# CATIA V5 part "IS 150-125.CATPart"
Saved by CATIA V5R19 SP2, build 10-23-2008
Part number: IS 150-125
Bounding box of the stored display mesh (mm): x -15.868 to 15.868, y -15.868 to 15.868, z 0 to 300
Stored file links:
  C:\Users\Bora\Desktop\3D Katı model\IS serisi\IS 150\IS 150-125.CATPart
  C:\Program Files\Dassault Systemes\B19\intel_a\reffiles\standard\MetricThickPitch.txt
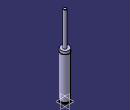
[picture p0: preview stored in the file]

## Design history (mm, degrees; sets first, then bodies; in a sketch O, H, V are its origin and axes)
Body1 (main body)
  Sketch1 on yz-plane, origin (0, 0, 0), H (0, 1, 0), V (0, 0, 1)
    point P3 (6, 299)
    point P5 (6, 299)
    point P7 (16, 163.5)
    point P8 (16, 161.5)
    point P12 (16, 161.5)
    point P13 (16, 163.5)
    line L1 (16, 0) -> (16, 4)
    line L2 (6, 299) -> (6, 173)
    arc A1 centre (5, 299) radius 1 from (6, 299) to (5, 300) ccw
    arc A2 centre (16, 162.5) radius 1 from (16, 163.5) to (16, 161.5) ccw
    line L3 (13.5, 7.5) -> (13.5, 4)
    line L4 (16, 7.5) -> (16, 161.5)
    line L5 (16, 163.5) -> (16, 173)
    line L6 (0, 0) -> (16, 0)
    line L7 (13.5, 4) -> (16, 4)
    line L8 (13.5, 7.5) -> (16, 7.5)
    line L9 (6, 173) -> (16, 173)
    line L10 (5, 300) -> (0, 300)
    point P15 (0, 300)
    horizontal: L6 H, L7 H, L8 H, L9 H
    coincidence: P15 V, P3 P5, P7 P13, P8 P12
    tangency: L10 A1
  Shaft1: profile Sketch1, axis Sketch1.V, angle 360
  Sketch2 on face of Shaft1 from Sketch1.L6, origin (0, 0, 0), H (1, 0, 0), V (0, -1, 0)
    point P1 (0, 0)
  Hole1: placed by Sketch2, at (0, 0, 0) direction (0, 0, 1), diameter 6.647, depth 7, threaded "M8", thread diameter 8, thread depth 7, pitch 1.25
